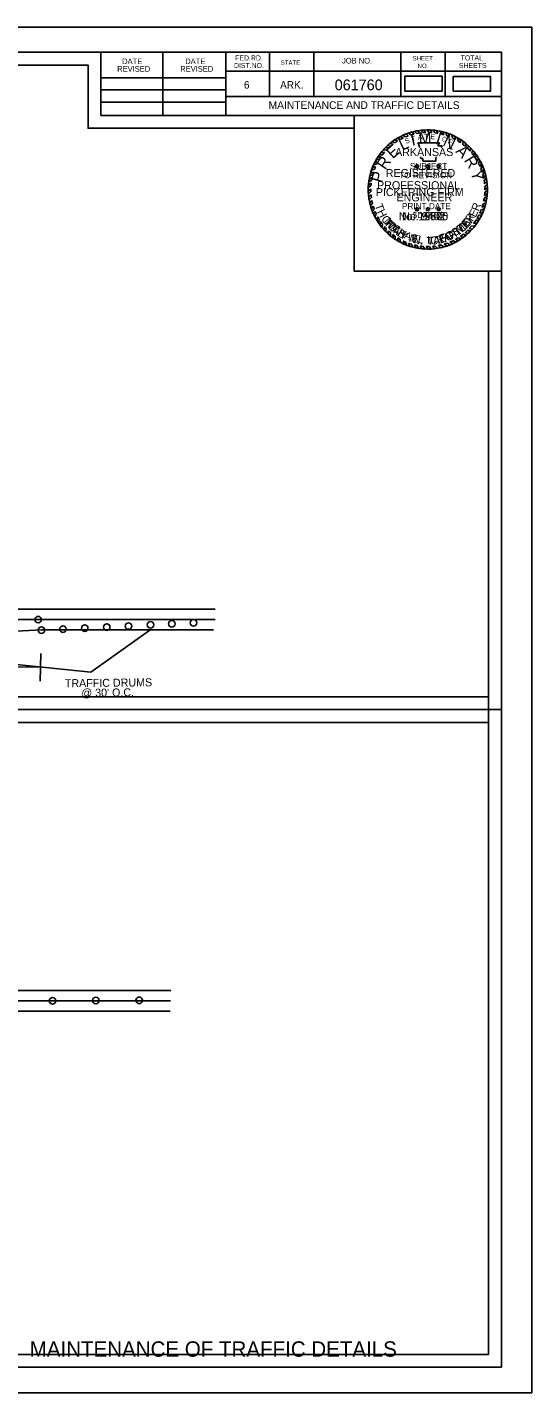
# Model space of a CAD drawing. Extents: x -500 to 213, y 382723 to 382830.
# Drawn here: x -8.3 to 31.1, y 382723.1 to 382829.8 of the extents above; entities that cross this region are included whole.
import ezdxf

# ---------------------------------------------------------------- set-up
doc = ezdxf.new("R2010")
doc.units = 0
for name, color, linetype in [('Default', 7, 'Continuous'), ('R_Border', 7, 'Continuous'), ('R_Border Notes', 7, 'Continuous'), ('R_Border Plan-Plan', 7, 'Continuous'), ('R_Border Title', 7, 'Continuous'), ('R_MOT', 7, 'Continuous'), ('R_No Plot', 7, 'Continuous'), ('STAMP_PE_CRAFTON', 7, 'Continuous'), ('STAMP_PE_FOSTER', 7, 'Continuous'), ('STAMP_PE_SEAL-INFO', 7, 'Continuous'), ('STAMP_PE_TAEGTMEYER', 7, 'Continuous'), ('STAMP_PE_TXT', 7, 'Continuous'), ('STAMP_PRELIMINARY', 7, 'Continuous')]:
    doc.layers.add(name, color=color, linetype=linetype)

# ---------------------------------------------------------------- blocks, each defined once
blk = doc.blocks.new('DOT')
at = {"layer": 'Default'}
blk.add_circle((-0.4, -0.3), 3.75, dxfattribs=at)

msp = doc.modelspace()

# ---------------------------------------------------------------- linework, layer by layer
at = {"layer": 'Default'}
for p, q in [((-97.81, 382784.35), (6.37, 382784.35)), ((-97.83, 382783.53), (6.35, 382783.53)), ((-24.28, 382781.9), (-7.21, 382782.72)), ((-7.21, 382782.72), (6.24, 382782.72)), ((-7.27, 382780.89), (-7.32, 382778.71)), ((-107.24, 382754.56), (2.89, 382754.56)), ((-107.26, 382753.75), (2.87, 382753.75)), ((-11.45, 382752.93), (2.85, 382752.93))]:
    msp.add_line(p, q, dxfattribs=at)
for points in [[(21.19, 382824.82), (24.1, 382824.82), (24.1, 382825.98), (21.19, 382825.98)], [(24.98, 382824.8), (27.89, 382824.8), (27.89, 382825.96), (24.98, 382825.96)]]:
    msp.add_lwpolyline(points, close=True, dxfattribs=at)
at = {"layer": 'R_Border'}
for p, q in [((-129.35, 382827.85), (28.74, 382827.85)), ((-2.58, 382822.91), (-2.58, 382827.85)), ((2.26, 382822.91), (2.26, 382827.85)), ((7.19, 382827.85), (7.19, 382822.91)), ((10.61, 382827.85), (10.61, 382824.38)), ((14.08, 382827.85), (14.08, 382824.38)), ((20.87, 382827.85), (20.87, 382824.38)), ((24.34, 382827.85), (24.34, 382824.38)), ((28.74, 382725.12), (28.74, 382827.85)), ((-2.58, 382825.84), (7.19, 382825.84)), ((28.74, 382826.38), (7.19, 382826.38)), ((28.74, 382826.39), (28.74, 382826.39)), ((-2.58, 382824.91), (7.19, 382824.91)), ((-2.58, 382823.94), (7.19, 382823.94)), ((28.74, 382824.38), (7.19, 382824.38)), ((8.67, 382824.38), (28.74, 382824.38)), ((28.74, 382822.91), (-2.58, 382822.91)), ((28.74, 382725.12), (-129.35, 382725.12))]:
    msp.add_line(p, q, dxfattribs=at)
at = {"layer": 'R_Border Plan-Plan'}
msp.add_line((-129.35, 382776.49), (28.74, 382776.49), dxfattribs=at)
at = {"layer": 'R_MOT'}
for p, q in [((1.24, 382782.69), (-3.36, 382779.43)), ((-23.33, 382781.45), (-3.36, 382779.43)), ((-24.32, 382779.92), (-7.29, 382779.8))]:
    msp.add_line(p, q, dxfattribs=at)
at = {"layer": 'R_No Plot'}
for points in [[(-135.56, 382829.8), (31.11, 382829.8), (31.11, 382723.13), (-135.56, 382723.13)], [(27.74, 382777.49), (-128.35, 382777.49), (-128.35, 382826.85), (-3.58, 382826.85), (-3.58, 382821.91), (5.19, 382821.91), (17.24, 382821.91), (17.24, 382810.74), (27.74, 382810.74)], [(-128.35, 382826.85), (-3.58, 382826.85), (-3.58, 382821.91), (5.19, 382821.91), (17.24, 382821.91), (17.24, 382810.74), (27.74, 382810.74), (27.74, 382726.12), (-128.35, 382726.12)], [(17.24, 382822.91), (28.74, 382822.91), (28.74, 382810.74), (17.24, 382810.74)], [(-128.35, 382775.49), (27.74, 382775.49), (27.74, 382726.12), (-128.35, 382726.12)]]:
    msp.add_lwpolyline(points, close=True, dxfattribs=at)
at = {"layer": 'STAMP_PE_SEAL-INFO'}
for p, q in [((21.47, 382821.54), (21.66, 382821.39)), ((21.76, 382821.63), (21.91, 382821.46)), ((21.96, 382821.68), (22.13, 382821.51)), ((22.2, 382821.73), (22.35, 382821.54)), ((22.46, 382821.76), (22.6, 382821.57)), ((22.82, 382821.59), (22.67, 382821.78)), ((23.07, 382821.59), (22.93, 382821.79)), ((23.3, 382821.58), (23.17, 382821.79)), ((23.55, 382821.55), (23.41, 382821.77)), ((23.77, 382821.52), (23.64, 382821.75)), ((24.05, 382821.46), (23.96, 382821.69)), ((24.25, 382821.41), (24.17, 382821.64)), ((24.47, 382821.33), (24.4, 382821.57)), ((19.84, 382820.57), (20.06, 382820.5)), ((20.01, 382820.72), (20.27, 382820.67)), ((20.2, 382820.88), (20.42, 382820.78)), ((20.41, 382821.01), (20.63, 382820.91)), ((20.6, 382821.14), (20.82, 382821.02)), ((20.82, 382821.26), (21.06, 382821.15)), ((21.04, 382821.37), (21.23, 382821.23)), ((21.29, 382821.47), (21.44, 382821.31)), ((22.22, 382820.78), (23.9, 382820.78)), ((22.28, 382820.62), (22.22, 382820.78)), ((22.34, 382820.47), (22.28, 382820.62)), ((22.34, 382820.42), (22.34, 382820.47)), ((23.9, 382820.78), (23.78, 382820.53)), ((23.78, 382820.53), (24.1, 382820.53)), ((24.1, 382820.53), (24.03, 382820.42)), ((24.68, 382821.25), (24.61, 382821.5)), ((24.91, 382821.15), (24.86, 382821.4)), ((25.14, 382821.04), (25.09, 382821.29)), ((25.33, 382820.92), (25.31, 382821.17)), ((25.55, 382820.78), (25.53, 382821.04)), ((25.73, 382820.65), (25.75, 382820.89)), ((25.95, 382820.46), (25.96, 382820.72)), ((26.11, 382820.31), (26.14, 382820.56)), ((18.95, 382819.47), (19.2, 382819.48)), ((19.08, 382819.67), (19.34, 382819.69)), ((19.19, 382819.84), (19.45, 382819.84)), ((19.33, 382820.03), (19.61, 382820.04)), ((19.51, 382820.23), (19.77, 382820.21)), ((19.67, 382820.4), (19.94, 382820.38)), ((22.44, 382819.56), (22.42, 382819.67)), ((22.59, 382819.56), (22.44, 382819.56)), ((22.59, 382819.35), (22.59, 382819.56)), ((23.62, 382819.52), (23.61, 382819.35)), ((23.65, 382819.67), (23.62, 382819.52)), ((26.29, 382820.13), (26.32, 382820.39)), ((26.42, 382819.97), (26.49, 382820.2)), ((26.59, 382819.76), (26.65, 382820.01)), ((26.7, 382819.6), (26.79, 382819.83)), ((26.85, 382819.35), (26.94, 382819.6)), ((26.95, 382819.17), (27.06, 382819.39)), ((18.5, 382818.39), (18.74, 382818.48)), ((18.58, 382818.64), (18.82, 382818.71)), ((18.65, 382818.85), (18.9, 382818.92)), ((18.74, 382819.06), (19, 382819.12)), ((18.84, 382819.26), (19.09, 382819.29)), ((23.61, 382819.35), (22.59, 382819.35)), ((27.07, 382818.93), (27.18, 382819.17)), ((27.14, 382818.76), (27.27, 382818.98)), ((27.23, 382818.49), (27.37, 382818.72)), ((27.29, 382818.3), (27.43, 382818.53)), ((18.54, 382817.41), (18.33, 382817.28)), ((18.56, 382817.62), (18.34, 382817.48)), ((18.59, 382817.84), (18.36, 382817.72)), ((18.63, 382818.07), (18.4, 382817.94)), ((18.45, 382818.19), (18.68, 382818.29)), ((27.35, 382818.02), (27.51, 382818.25)), ((27.39, 382817.83), (27.56, 382818.01)), ((27.42, 382817.58), (27.61, 382817.75)), ((27.44, 382817.37), (27.63, 382817.52)), ((27.44, 382817.11), (27.65, 382817.27)), ((18.53, 382817.16), (18.33, 382816.99)), ((18.53, 382816.96), (18.34, 382816.79)), ((18.55, 382816.71), (18.36, 382816.53)), ((18.58, 382816.49), (18.4, 382816.31)), ((18.62, 382816.26), (18.45, 382816.08)), ((27.35, 382816.21), (27.58, 382816.31)), ((27.39, 382816.46), (27.61, 382816.57)), ((27.42, 382816.66), (27.64, 382816.78)), ((27.44, 382816.91), (27.65, 382817.05)), ((18.66, 382816.05), (18.51, 382815.85)), ((18.72, 382815.83), (18.58, 382815.62)), ((18.79, 382815.62), (18.65, 382815.41)), ((18.88, 382815.41), (18.75, 382815.2)), ((18.96, 382815.21), (18.85, 382814.98)), ((26.97, 382815.12), (27.21, 382815.16)), ((27.05, 382815.29), (27.29, 382815.34)), ((27.15, 382815.55), (27.39, 382815.61)), ((27.22, 382815.74), (27.47, 382815.84)), ((27.29, 382815.99), (27.53, 382816.09)), ((19.08, 382814.99), (18.99, 382814.74)), ((19.2, 382814.78), (19.11, 382814.55)), ((19.3, 382814.63), (19.25, 382814.35)), ((19.44, 382814.43), (19.39, 382814.17)), ((19.59, 382814.24), (19.55, 382813.98)), ((19.74, 382814.07), (19.71, 382813.81)), ((26.23, 382814.07), (26.47, 382814.03)), ((26.42, 382814.29), (26.65, 382814.25)), ((26.57, 382814.49), (26.83, 382814.49)), ((26.74, 382814.73), (26.98, 382814.73)), ((26.83, 382814.87), (27.08, 382814.9)), ((19.9, 382813.91), (19.89, 382813.65)), ((20.08, 382813.76), (20.08, 382813.49)), ((20.26, 382813.61), (20.27, 382813.35)), ((20.43, 382813.48), (20.44, 382813.22)), ((20.64, 382813.34), (20.67, 382813.09)), ((20.82, 382813.24), (20.86, 382812.98)), ((21.06, 382813.12), (21.13, 382812.85)), ((21.24, 382813.03), (21.33, 382812.78)), ((24.72, 382813.03), (24.93, 382812.9)), ((24.95, 382813.13), (25.19, 382813.02)), ((25.15, 382813.24), (25.36, 382813.12)), ((25.36, 382813.36), (25.58, 382813.26)), ((25.53, 382813.47), (25.75, 382813.38)), ((25.76, 382813.64), (26, 382813.57)), ((25.9, 382813.76), (26.13, 382813.69)), ((26.1, 382813.94), (26.32, 382813.87)), ((21.49, 382812.93), (21.59, 382812.68)), ((21.69, 382812.87), (21.81, 382812.62)), ((21.95, 382812.8), (22.05, 382812.56)), ((22.15, 382812.76), (22.27, 382812.53)), ((22.4, 382812.71), (22.52, 382812.49)), ((22.61, 382812.69), (22.75, 382812.48)), ((22.86, 382812.68), (23.01, 382812.47)), ((23.09, 382812.68), (23.26, 382812.48)), ((23.35, 382812.69), (23.51, 382812.5)), ((23.56, 382812.71), (23.75, 382812.53)), ((23.79, 382812.75), (23.98, 382812.58)), ((24.03, 382812.8), (24.22, 382812.64)), ((24.26, 382812.86), (24.47, 382812.71)), ((24.51, 382812.94), (24.73, 382812.81))]:
    msp.add_line(p, q, dxfattribs=at)
for radius, start, end in [(4.66, 105.2339, 109.0352), (4.66, 99.7525, 102.7765), (4.46, 98.258, 101.0329), (4.66, 93.9381, 96.5517), (4.46, 92.1102, 95.0367), (4.66, 87.7298, 90.6707), (4.46, 85.9628, 88.9097), (4.66, 81.9732, 84.8236), (4.46, 79.9264, 82.696), (4.66, 75.3125, 77.9426), (4.66, 69.6061, 72.3058), (4.66, 129.7326, 132.5376), (4.46, 127.5297, 130.9683), (4.66, 123.6199, 126.5906), (4.46, 121.9746, 125.11), (4.66, 117.6544, 120.8099), (4.46, 115.6869, 119.1583), (4.66, 111.3124, 114.7026), (4.46, 110.3086, 113.1659), (4.46, 104.0352, 107.3615), (4.46, 73.5575, 76.2314), (4.46, 67.6248, 70.504), (4.66, 63.1329, 66.2704), (4.46, 61.1558, 64.3784), (4.66, 56.9003, 60.0942), (4.46, 54.9238, 58.2702), (4.46, 48.3016, 52.0395), (4.66, 50.3492, 53.7159), (4.66, 44.3405, 47.3929), (4.66, 147.0072, 149.899), (4.66, 141.6056, 144.4486), (4.46, 145.0197, 148.2104), (4.46, 139.301, 142.5873), (4.66, 135.4021, 138.3031), (4.46, 133.1331, 136.2562), (4.46, 42.2212, 45.5512), (4.46, 36.135, 39.5311), (4.66, 38.1247, 41.2316), (4.46, 29.9032, 33.6645), (4.66, 31.9614, 35.4294), (4.66, 25.9391, 29.0125), (4.66, 164.3068, 166.894), (4.66, 158.4077, 161.0701), (4.46, 162.4331, 165.0013), (4.66, 152.864, 155.5189), (4.46, 156.3402, 159.2319), (4.46, 151.0315, 153.573), (4.46, 23.7732, 27.2211), (4.46, 17.6802, 21.4251), (4.66, 19.9538, 23.3141), (4.66, 13.8421, 17.4447), (4.66, 175.7409, 178.2066), (4.66, 170.0003, 172.6878), (4.46, 173.73, 176.4734), (4.46, 167.9048, 170.9039), (4.46, 11.5444, 15.2364), (4.46, 5.7599, 9.0606), (4.46, 359.7329, 3.0639), (4.66, 7.5852, 10.8621), (4.66, 1.7215, 4.7268), (4.66, 181.7251, 184.1626), (4.66, 187.4204, 190.1927), (4.46, 179.6454, 182.2633), (4.46, 185.4539, 188.234), (4.46, 191.2274, 193.9858), (4.46, 348.0778, 351.3435), (4.46, 353.8632, 357.1274), (4.66, 349.8305, 353.0885), (4.66, 355.7156, 358.9569), (4.66, 193.0369, 195.9973), (4.66, 198.8967, 201.6281), (4.46, 196.9675, 199.8353), (4.66, 204.5479, 207.4328), (4.46, 202.7761, 205.4791), (4.46, 329.5549, 333.2076), (4.46, 335.6038, 339.1858), (4.66, 331.4037, 334.9332), (4.46, 341.777, 345.0925), (4.66, 337.3837, 340.9933), (4.66, 343.8925, 347.035), (4.66, 210.8636, 213.6571), (4.46, 208.7883, 211.7934), (4.66, 216.6115, 219.491), (4.46, 214.1838, 217.2747), (4.46, 220.3909, 223.3056), (4.46, 316.6531, 320.3711), (4.66, 318.2846, 321.8043), (4.46, 323.5851, 327.4407), (4.66, 325.4405, 328.9872), (4.66, 222.48, 225.3801), (4.66, 228.3665, 231.348), (4.46, 226.2494, 229.2407), (4.46, 232.229, 234.9336), (4.66, 234.295, 236.9452), (4.46, 238.2223, 240.8353), (4.66, 240.1977, 242.8613), (4.46, 244.3204, 246.9486), (4.46, 292.8745, 296.1185), (4.66, 294.6481, 298.2166), (4.46, 299.0768, 302.1724), (4.66, 300.621, 303.8703), (4.46, 304.823, 308.5143), (4.66, 306.3721, 310.208), (4.46, 310.7744, 314.3161), (4.66, 312.4518, 315.6633), (4.66, 246.576, 249.1558), (4.46, 250.3491, 253.1216), (4.66, 252.5967, 255.3252), (4.46, 256.505, 259.1192), (4.66, 258.4433, 261.1398), (4.46, 262.3783, 265.2012), (4.66, 264.1978, 267.1009), (4.46, 268.3215, 271.277), (4.66, 270.2548, 273.3361), (4.46, 274.6157, 277.4486), (4.66, 276.4239, 279.4357), (4.46, 280.3459, 283.5814), (4.66, 282.3199, 285.3702), (4.46, 286.6423, 289.9783), (4.66, 288.5709, 291.9733)]:
    msp.add_arc((22.99, 382817.13), radius, start, end, dxfattribs=at)
at = {"layer": 'STAMP_PE_TXT'}
for p, q in [((22.08, 382818.92), (21.98, 382818.99)), ((21.98, 382818.99), (22.1, 382818.99)), ((22.04, 382818.8), (22.08, 382818.92)), ((22.14, 382818.87), (22.04, 382818.8)), ((22.1, 382818.99), (22.14, 382819.11)), ((22.14, 382819.11), (22.18, 382818.99)), ((22.24, 382818.8), (22.14, 382818.87)), ((22.18, 382818.99), (22.3, 382818.99)), ((22.3, 382818.99), (22.2, 382818.92)), ((22.2, 382818.92), (22.24, 382818.8)), ((22.93, 382818.92), (22.83, 382818.99)), ((22.83, 382818.99), (22.95, 382818.99)), ((22.89, 382818.8), (22.93, 382818.92)), ((22.99, 382818.87), (22.89, 382818.8)), ((22.95, 382818.99), (22.99, 382819.11)), ((22.99, 382819.11), (23.02, 382818.99)), ((23.09, 382818.8), (22.99, 382818.87)), ((23.02, 382818.99), (23.15, 382818.99)), ((23.15, 382818.99), (23.05, 382818.92)), ((23.05, 382818.92), (23.09, 382818.8)), ((23.77, 382818.92), (23.68, 382818.99)), ((23.68, 382818.99), (23.8, 382818.99)), ((23.74, 382818.8), (23.77, 382818.92)), ((23.84, 382818.87), (23.74, 382818.8)), ((23.8, 382818.99), (23.84, 382819.11)), ((23.84, 382819.11), (23.87, 382818.99)), ((23.94, 382818.8), (23.84, 382818.87)), ((23.87, 382818.99), (24, 382818.99)), ((24, 382818.99), (23.9, 382818.92)), ((23.9, 382818.92), (23.94, 382818.8)), ((22.08, 382815.56), (21.98, 382815.64)), ((21.98, 382815.64), (22.1, 382815.64)), ((22.04, 382815.45), (22.08, 382815.56)), ((22.14, 382815.52), (22.04, 382815.45)), ((22.1, 382815.64), (22.14, 382815.75)), ((22.14, 382815.75), (22.18, 382815.64)), ((22.24, 382815.45), (22.14, 382815.52)), ((22.18, 382815.64), (22.3, 382815.64)), ((22.3, 382815.64), (22.2, 382815.56)), ((22.2, 382815.56), (22.24, 382815.45)), ((22.93, 382815.56), (22.83, 382815.64)), ((22.83, 382815.64), (22.95, 382815.64)), ((22.89, 382815.45), (22.93, 382815.56)), ((22.99, 382815.52), (22.89, 382815.45)), ((22.95, 382815.64), (22.99, 382815.75)), ((22.99, 382815.75), (23.02, 382815.64)), ((23.09, 382815.45), (22.99, 382815.52)), ((23.02, 382815.64), (23.15, 382815.64)), ((23.15, 382815.64), (23.05, 382815.56)), ((23.05, 382815.56), (23.09, 382815.45)), ((23.77, 382815.56), (23.68, 382815.64)), ((23.68, 382815.64), (23.8, 382815.64)), ((23.74, 382815.45), (23.77, 382815.56)), ((23.84, 382815.52), (23.74, 382815.45)), ((23.8, 382815.64), (23.84, 382815.75)), ((23.84, 382815.75), (23.87, 382815.64)), ((23.94, 382815.45), (23.84, 382815.52)), ((23.87, 382815.64), (24, 382815.64)), ((24, 382815.64), (23.9, 382815.56)), ((23.9, 382815.56), (23.94, 382815.45))]:
    msp.add_line(p, q, dxfattribs=at)
at = {"layer": 'STAMP_PRELIMINARY'}
msp.add_circle((22.99, 382817.13), 4.66, dxfattribs=at)

# ---------------------------------------------------------------- block references
at = {"layer": 'R_MOT'}
for p, xscale, yscale, rotation in [((-7.45, 382783.54), 0.06809210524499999, 0.06809210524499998, -4.676990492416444), ((-3.81, 382782.88), 0.06809210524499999, 0.06809210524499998, -4.676990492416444), ((-2.09, 382782.96), 0.06809210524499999, 0.06809210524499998, -4.676990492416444), ((-0.39, 382783.04), 0.06809210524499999, 0.06809210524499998, -4.676990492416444), ((1.33, 382783.13), 0.06809210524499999, 0.06809210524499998, -4.676990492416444), ((3, 382783.21), 0.06809210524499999, 0.06809210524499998, -4.676990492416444), ((4.7, 382783.29), 0.06809210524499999, 0.06809210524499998, -4.676990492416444), ((-7.2, 382782.72), 0.06809210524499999, 0.06809210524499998, -4.676990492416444), ((-5.51, 382782.8), 0.06809210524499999, 0.06809210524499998, -4.676990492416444), ((-6.32, 382753.76), 0.06809210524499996, 0.06809210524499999, -4.676990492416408), ((-2.94, 382753.78), 0.06809210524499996, 0.06809210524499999, -4.676990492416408), ((0.45, 382753.8), 0.06809210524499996, 0.06809210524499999, -4.676990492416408)]:
    msp.add_blockref('DOT', p, dxfattribs=dict(at, xscale=xscale, yscale=yscale, rotation=rotation))

# ---------------------------------------------------------------- texts
at = {"layer": 'R_Border'}
for s, height, p in [('DATE', 0.44, (-0.91, 382826.92)), ('DATE', 0.44, (4.02, 382826.92)), ('DIST.NO.', 0.391, (7.83, 382826.62)), ('FED.RD.', 0.391, (7.93, 382827.21)), ('STATE', 0.342, (11.49, 382826.87)), ('JOB NO.', 0.44, (16.28, 382826.97)), ('SHEET', 0.342, (21.8, 382827.21)), ('NO.', 0.342, (22.19, 382826.62)), ('SHEETS', 0.391, (25.42, 382826.62)), ('TOTAL', 0.391, (25.56, 382827.21)), ('REVISED', 0.44, (-1.3, 382826.33)), ('REVISED', 0.44, (3.63, 382826.33)), ('6', 0.586, (8.61, 382825.01)), ('ARK.', 0.586, (11.44, 382825.01))]:
    msp.add_text(s, height=height, dxfattribs=at).set_placement(p)
at = {"layer": 'R_Border Notes'}
for s, height, p in [('061760', 0.84, (15.71, 382824.88)), ('MAINTENANCE AND TRAFFIC DETAILS', 0.6, (10.54, 382823.42))]:
    msp.add_text(s, height=height, dxfattribs=at).set_placement(p)
at = {"layer": 'R_Border Title'}
msp.add_text('MAINTENANCE OF TRAFFIC DETAILS', height=1.2, dxfattribs=at).set_placement((-8.14, 382725.94))
at = {"layer": 'R_MOT'}
for s, p in [('TRAFFIC DRUMS ', (-5.39, 382778.24)), ("@ 30' O.C.", (-4.1, 382777.49))]:
    msp.add_text(s, height=0.625, rotation=0.6305, dxfattribs=at).set_placement(p)
at = {"layer": 'STAMP_PE_CRAFTON'}
msp.add_text('No. 12370', height=0.625, dxfattribs=at).set_placement((20.72, 382814.73))
for s, rotation, p in [('T', 310.7442, (19.47, 382814.58)), ('O', 317.6422, (19.8, 382814.17)), ('N', 324.4537, (20.23, 382813.78)), ('T', 34.1136, (25.28, 382813.45)), ('O', 41.8391, (25.7, 382813.75)), ('N', 49.2411, (26.13, 382814.14)), ('Y', 331.1686, (20.74, 382813.42)), ('N', 347.4752, (21.77, 382812.97)), ('C', 6.0117, (23.22, 382812.8)), ('R', 14.8189, (23.77, 382812.86)), ('A', 20.5125, (24.33, 382813.01)), ('F', 28.7821, (24.82, 382813.2)), ('.', 356.8926, (22.38, 382812.83))]:
    msp.add_text(s, height=0.625, rotation=rotation, dxfattribs=at).set_placement(p)
at = {"layer": 'STAMP_PE_FOSTER'}
msp.add_text('No. 9402', height=0.625, dxfattribs=at).set_placement((20.98, 382814.73))
for s, rotation, p in [('R', 54.5031, (26.35, 382814.54)), ('M', 308.339, (19.54, 382814.64)), ('I', 314.1842, (19.94, 382814.17)), ('C', 319.8733, (20.12, 382814)), ('H', 327.7235, (20.59, 382813.63)), ('S', 31.7234, (25.08, 382813.44)), ('T', 39.4194, (25.56, 382813.75)), ('E', 46.9613, (25.99, 382814.13)), ('A', 335.7276, (21.08, 382813.34)), ('E', 343.5779, (21.64, 382813.1)), ('L', 350.8115, (22.17, 382812.96)), ('L', 1.2666, (22.94, 382812.89)), ('.', 6.8035, (23.47, 382812.92)), ('F', 15.8691, (24, 382813.01)), ('O', 23.719, (24.53, 382813.17))]:
    msp.add_text(s, height=0.6, rotation=rotation, dxfattribs=at).set_placement(p)
at = {"layer": 'STAMP_PE_TAEGTMEYER'}
for s, rotation, p in [('T', 289.646, (18.83, 382815.89)), ('H', 296.7339, (19.01, 382815.39)), ('Y', 53.9986, (26.38, 382814.43)), ('E', 63.0984, (26.71, 382814.9)), ('R', 69.57, (26.96, 382815.39)), ('O', 303.7708, (19.31, 382814.84)), ('M', 314.2033, (19.64, 382814.36)), ('A', 321.0594, (20.12, 382813.88)), ('T', 31.466, (25.04, 382813.31)), ('M', 39.3, (25.49, 382813.58)), ('E', 46.8094, (26.01, 382814.02)), ('S', 327.8239, (20.53, 382813.56)), ('N', 344.2727, (21.48, 382813.06)), ('T', 3.0061, (22.92, 382812.79)), ('A', 8.9826, (23.44, 382812.82)), ('E', 17.6836, (23.96, 382812.9)), ('G', 23.3052, (24.49, 382813.06)), ('.', 350.6464, (22.09, 382812.89))]:
    msp.add_text(s, height=0.625, rotation=rotation, dxfattribs=at).set_placement(p)
msp.add_text('No. 19605', height=0.625, dxfattribs=at).set_placement((20.72, 382814.73))
at = {"layer": 'STAMP_PE_TXT'}
for s, rotation, p in [('S', 23.5541, (21.29, 382820.68)), ('T', 16.311, (21.75, 382820.87)), ('A', 9.0679, (22.23, 382821)), ('T', 1.8248, (22.72, 382821.06)), ('E', 355.2002, (23.18, 382821.07)), ('O', 342.2506, (24.04, 382820.93)), ('F', 335.0075, (24.52, 382820.76))]:
    msp.add_text(s, height=0.391, rotation=rotation, dxfattribs=at).set_placement(p)
for s, p in [('ARKANSAS', (20.43, 382819.74)), ('REGISTERED', (19.7, 382818.1)), ('PROFESSIONAL', (19.02, 382817.15)), ('ENGINEER', (20.54, 382816.2))]:
    msp.add_text(s, height=0.625, dxfattribs=at).set_placement(p)
at = {"layer": 'STAMP_PRELIMINARY'}
for s, rotation, p in [('M', 3.1074, (22.3, 382820.68)), ('I', 342.3164, (23.54, 382820.71)), ('E', 42.3578, (20.25, 382819.48)), ('L', 25.513, (20.99, 382820.15)), ('I', 12.5248, (21.76, 382820.53)), ('N', 333.9382, (24.09, 382820.58)), ('A', 315.6579, (25.11, 382820.06)), ('R', 56.2292, (19.67, 382818.61)), ('R', 301.3831, (25.79, 382819.41)), ('P', 73.913, (19.4, 382817.6)), ('Y', 283.2593, (26.34, 382818.51))]:
    msp.add_text(s, height=0.9, rotation=rotation, dxfattribs=at).set_placement(p)
for s, height, p in [('TO REVISION', 0.48, (20.75, 382818.01)), ('SUBJECT', 0.48, (21.59, 382818.71)), ('PICKERING FIRM', 0.625, (18.92, 382816.61)), ('PRINT DATE', 0.48, (20.97, 382815.59)), ('$DATE$', 0.48, (21.8, 382814.9))]:
    msp.add_text(s, height=height, dxfattribs=at).set_placement(p)

doc.saveas('drawing.dxf')
